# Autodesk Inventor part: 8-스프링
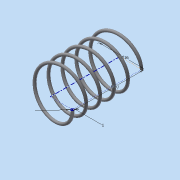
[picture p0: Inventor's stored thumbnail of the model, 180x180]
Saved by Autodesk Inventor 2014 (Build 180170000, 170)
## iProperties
Created: 2015-06
Part Number: 8-스프링
Material: 강철, 연강
Document SubType Name: Modeling
Designer: MYHOME
Density: 1 g/cm^3
Appearance: 강철
Author: MYHOME
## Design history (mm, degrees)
sketch "스케치1"
  geometry: L1 (0, 0)-(8, 0); L2 (8, 0)-(8, 21.5); L3 (8, 21.5)-(0, 21.5); L4 (0, 21.5)-(0, 0); C1 r 0.5 at (8, 0)
  constraints: 8 end point, 2 parallel, 1 centre point, 1 coincident, 1 horizontal, 1 perpendicular
  dimensions: "d0" = 1 diameter of C1; "d1" = 16 diameter of L2 L4; "d2" = 21.5 distance of L1.end L2.end (derived)
feature "코일1" sketch "스케치1" pitch "d3" = 10; turns "d5" = 5; dims "d4" = 21.5 (= d2), "d6" = 0, angle "d7" = 90 deg, angle "d8" = 90 deg, "d9" = 0, "d10" = 0
sketch "스케치2"
  geometry: L1 (-8.5, 0)-(-7.5, 0) reference; 1 further point
  constraints: 1 horizontal alignment
extrude "돌출1" cut sketch "스케치2" stored distance "d11" = 10; taper "d12" = 0 deg
node "작업 평면1"
sketch "스케치3"
  geometry: L1 (-7.5, 0)-(-8.5, 0) reference; 1 further point
  constraints: 1 horizontal alignment
extrude "돌출2" cut sketch "스케치3" stored distance "d14" = 10; taper "d15" = 0 deg
node "솔리드1"
node "절단 모서리 투영1"
node "절단 모서리 투영2"
other parameters: "d13" = 21.5 (= d2)
